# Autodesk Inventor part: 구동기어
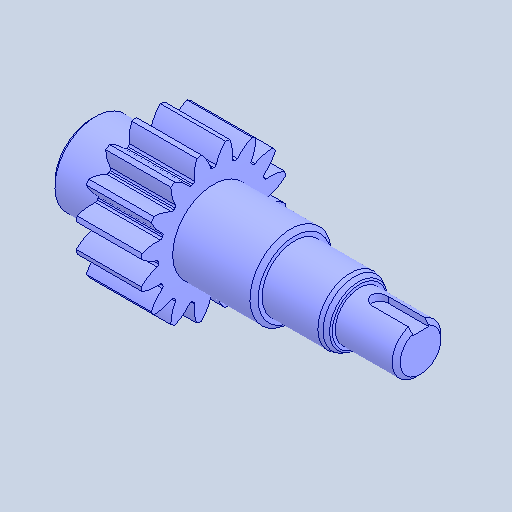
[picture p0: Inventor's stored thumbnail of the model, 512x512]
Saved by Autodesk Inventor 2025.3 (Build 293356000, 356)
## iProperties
Created: 2025-10
Part Number: 구동기어
Material: 강철, 합금
Document SubType Name: Modeling
Designer: PC-04
Density: 7.73 g/cm^3
Appearance: 기본값
Author: jhkim
Sending System: Autodesk Inventor 2026
Preprocessor: ST-DEVELOPER v20.1
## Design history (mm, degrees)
feature "솔리드1"
node "솔리드2"
